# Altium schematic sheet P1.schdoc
size 594 x 419 mm; Symbol: Sheet-Symbol_A4; Company: 嘉立创EDA; Version: V1.0; Page Size: A4; @Project Name: fin; @Page Count: 1; @Update Date: 2026-05-17; @Create Date: 2026-05-17; @Schematic Name: Schematic1; @Page No: 1; @Page Name: P1; Device: Sheet-Symbol_A4; Border: 1; Title Block Position: 3; Width: 2338; Height: 1652; Region Start: 1; X Region Count: 6; Y Region Count: 4; Blade Width: 10; @Board Name: Board1; @Create Time: 12:38:21; @Update Time: 12:38:21
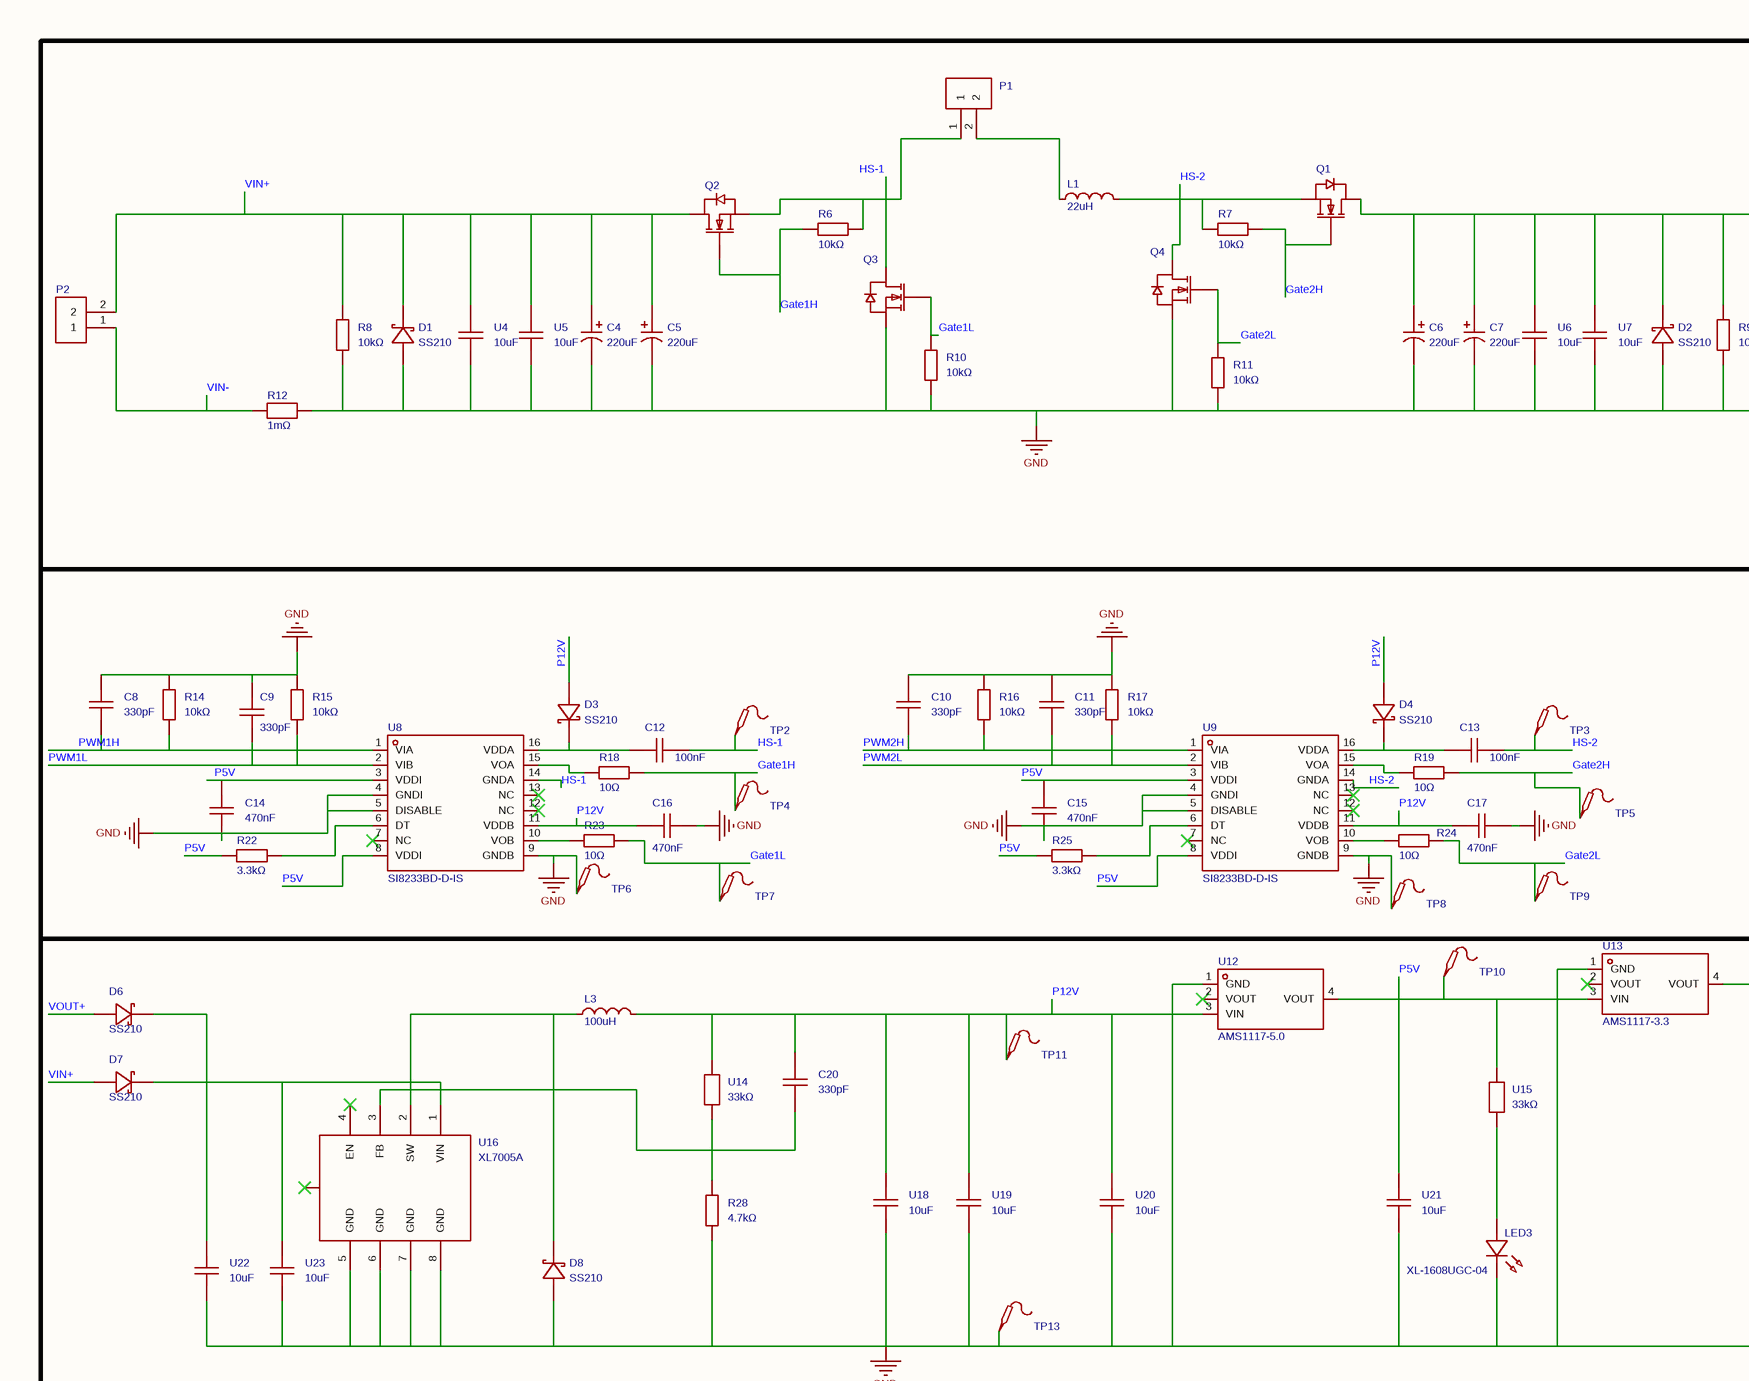
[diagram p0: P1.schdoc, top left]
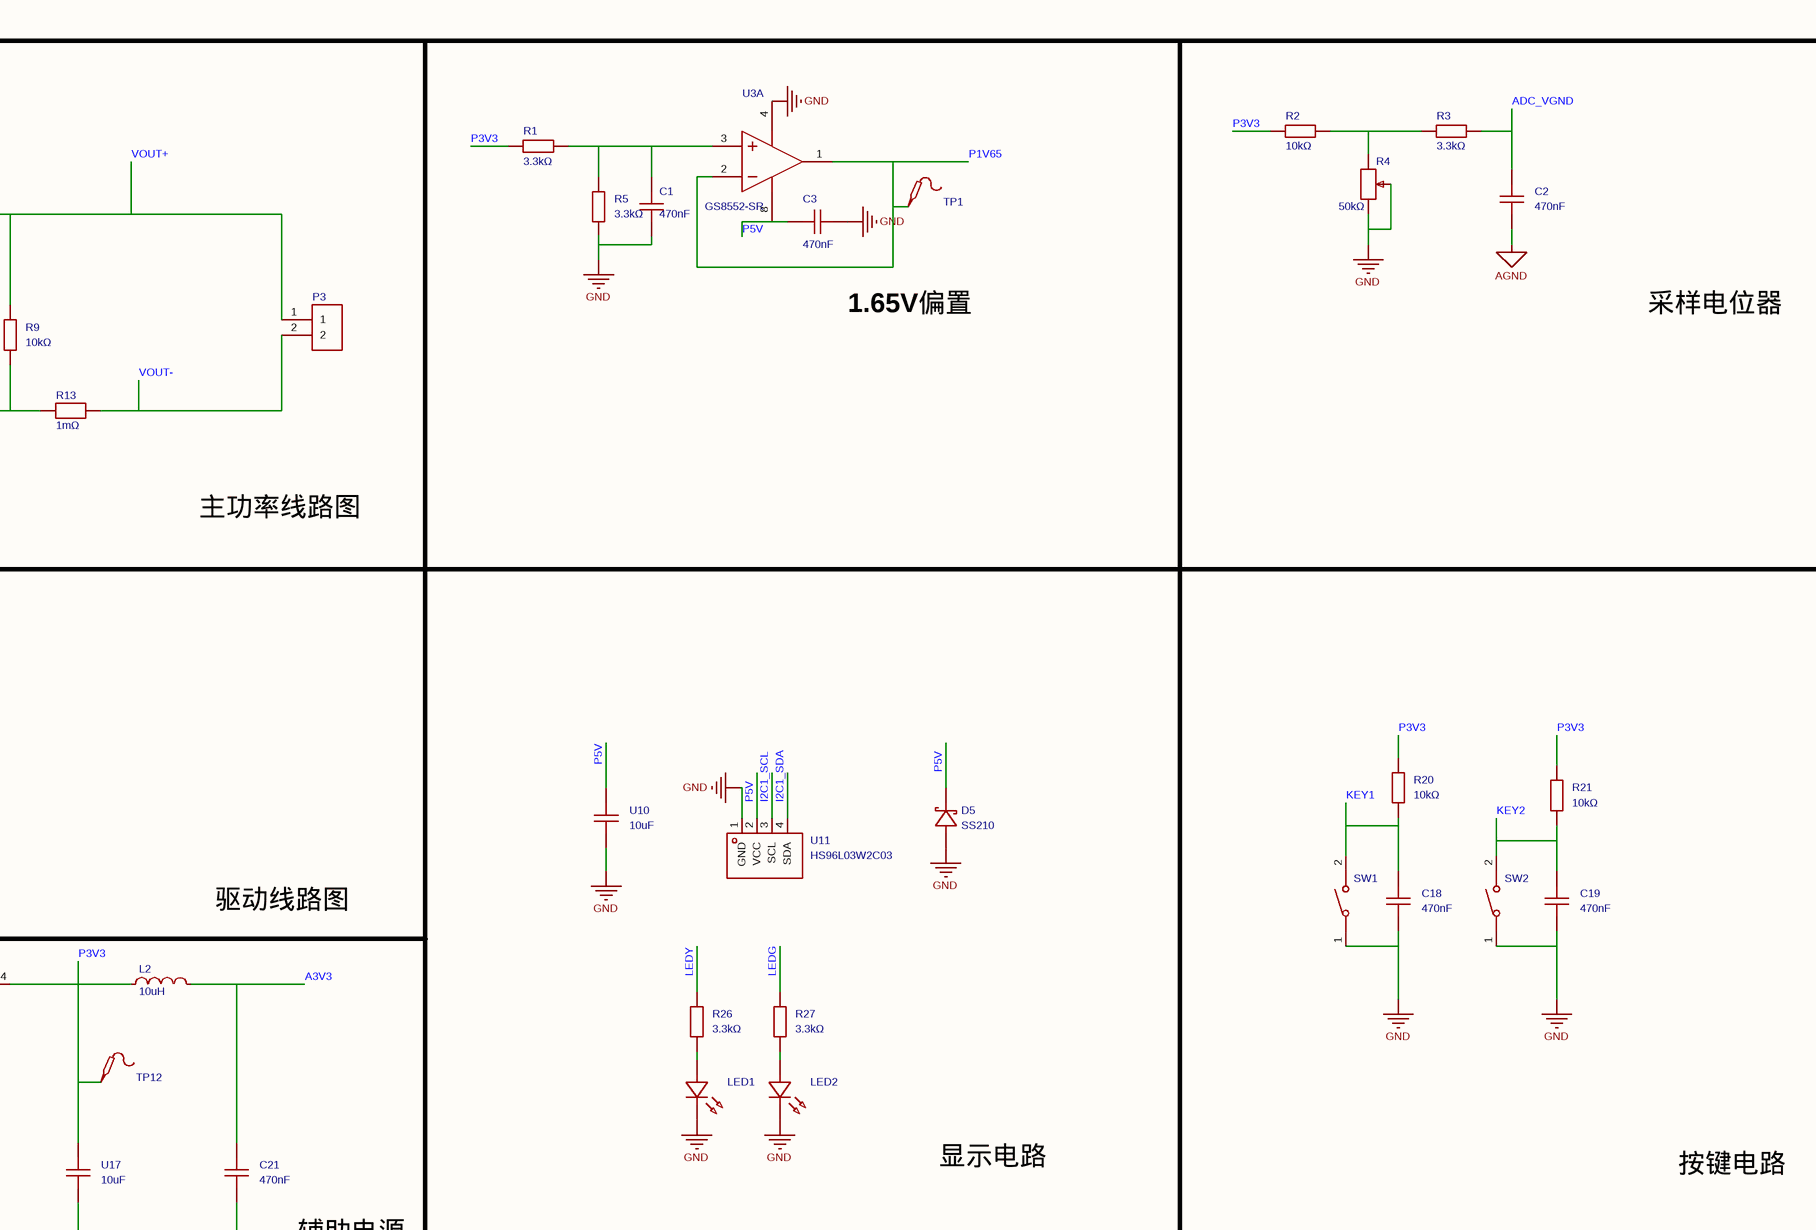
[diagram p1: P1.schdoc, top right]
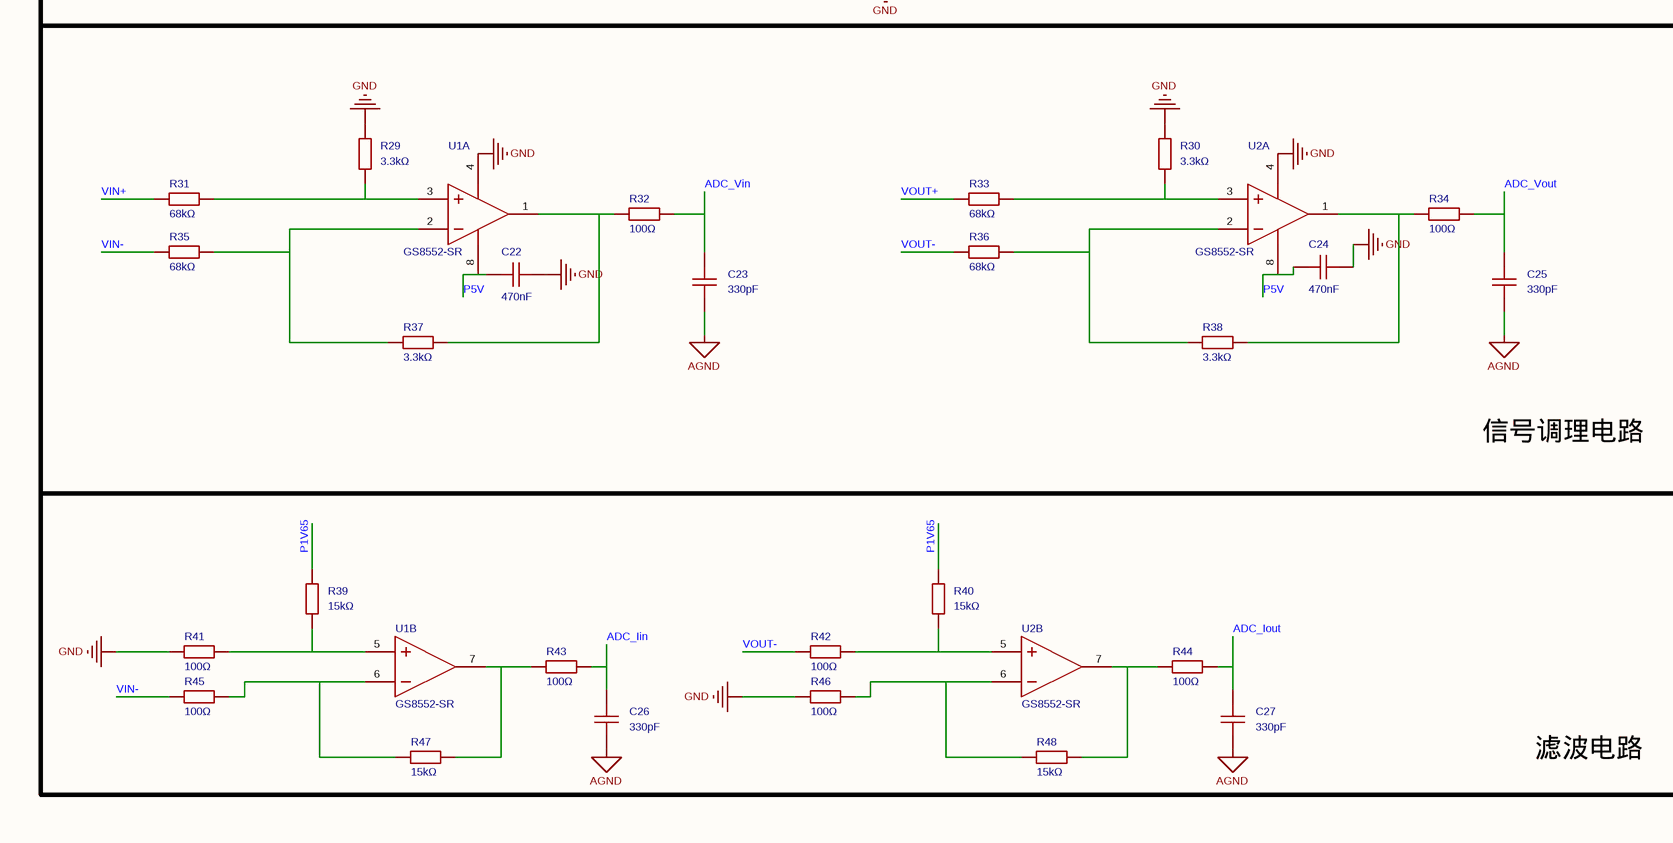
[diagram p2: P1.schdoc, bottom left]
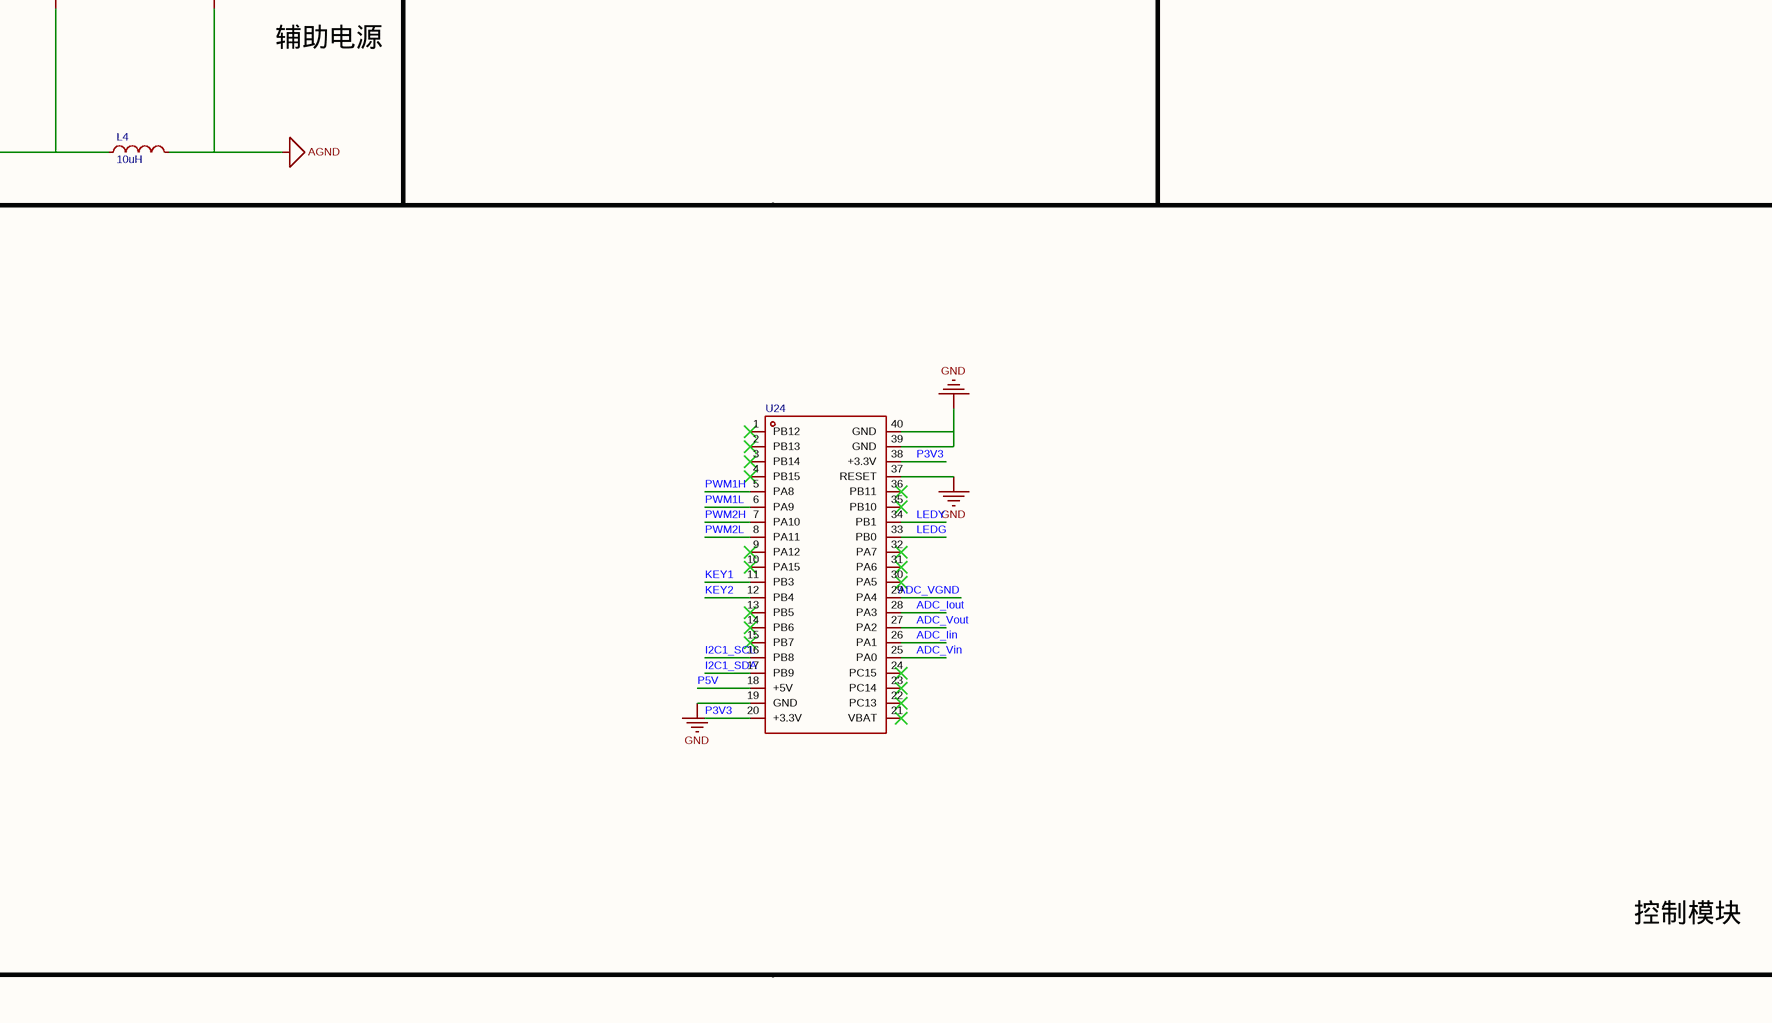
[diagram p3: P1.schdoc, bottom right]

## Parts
C1  470nF  [CAP-TH_L6.0-W5.0-P5.08-D0.5]
C2  470nF  [CAP-TH_L6.0-W5.0-P5.08-D0.5]
C3  470nF  [CAP-TH_L6.0-W5.0-P5.08-D0.5]
C4  220uF  [CAP-SMD_BD10.0-L10.3-W10.3-FD-LS11.0]
C5  220uF  [CAP-SMD_BD10.0-L10.3-W10.3-FD-LS11.0]
C6  220uF  [CAP-SMD_BD10.0-L10.3-W10.3-FD-LS11.0]
C7  220uF  [CAP-SMD_BD10.0-L10.3-W10.3-FD-LS11.0]
C8  330pF  [CAP-TH_L4.9-W3.7-P5.08-D0.5]
C9  330pF  [CAP-TH_L4.9-W3.7-P5.08-D0.5]
C10  330pF  [CAP-TH_L4.9-W3.7-P5.08-D0.5]
C11  330pF  [CAP-TH_L4.9-W3.7-P5.08-D0.5]
C12  100nF  [CAP-TH_L5.8-W3.6-P5.0-D0.6]
C13  100nF  [CAP-TH_L5.8-W3.6-P5.0-D0.6]
C14  470nF  [CAP-TH_L6.0-W5.0-P5.08-D0.5]
C15  470nF  [CAP-TH_L6.0-W5.0-P5.08-D0.5]
C16  470nF  [CAP-TH_L6.0-W5.0-P5.08-D0.5]
C17  470nF  [CAP-TH_L6.0-W5.0-P5.08-D0.5]
C18  470nF  [CAP-TH_L6.0-W5.0-P5.08-D0.5]
C19  470nF  [CAP-TH_L6.0-W5.0-P5.08-D0.5]
C20  330pF  [CAP-TH_L4.9-W3.7-P5.08-D0.5]
C21  470nF  [CAP-TH_L6.0-W5.0-P5.08-D0.5]
C22  470nF  [CAP-TH_L6.0-W5.0-P5.08-D0.5]
C23  330pF  [CAP-TH_L4.9-W3.7-P5.08-D0.5]
C24  470nF  [CAP-TH_L6.0-W5.0-P5.08-D0.5]
C25  330pF  [CAP-TH_L4.9-W3.7-P5.08-D0.5]
C26  330pF  [CAP-TH_L4.9-W3.7-P5.08-D0.5]
C27  330pF  [CAP-TH_L4.9-W3.7-P5.08-D0.5]
D1  SS210  [SMA_L4.3-W2.6-LS5.0-RD]
D2  SS210  [SMA_L4.3-W2.6-LS5.0-RD]
D3  SS210  [SMA_L4.3-W2.6-LS5.0-RD]
D4  SS210  [SMA_L4.3-W2.6-LS5.0-RD]
D5  SS210  [SMA_L4.3-W2.6-LS5.0-RD]
D6  SS210  [SMA_L4.3-W2.6-LS5.0-RD]
D7  SS210  [SMA_L4.3-W2.6-LS5.0-RD]
D8  SS210  [SMA_L4.3-W2.6-LS5.0-RD]
L1  22uH  [IND-SMD_2P-L16.9-W16.9]
L2  10uH  [L0603]
L3  100uH  [IND-SMD_L6.0-W6.0_CR6020]
L4  10uH  [L0603]
LED1  XL-1608UYC-06  [LED0603-RD-YELLOW]  (value not drawn)
LED2  XL-1608UGC-04  [LED0603-RD_GREEN]  (value not drawn)
LED3  XL-1608UGC-04  [LED0603-RD_GREEN]
P1  WJ500V-5.08-2P  [CONN-TH_2P-P5.00_WJ500V-5.08-2P]  (value not drawn)
P2  WJ500V-5.08-2P  [CONN-TH_2P-P5.00_WJ500V-5.08-2P]  (value not drawn)
P3  WJ500V-5.08-2P  [CONN-TH_2P-P5.00_WJ500V-5.08-2P]  (value not drawn)
Q1  IRFP4468PBF  [TO-247AC-3_L15.8-W5.0-P5.46-L]  (value not drawn)
Q2  IRFP4468PBF  [TO-247AC-3_L15.8-W5.0-P5.46-L]  (value not drawn)
Q3  IRFP4468PBF  [TO-247AC-3_L15.8-W5.0-P5.46-L]  (value not drawn)
Q4  IRFP4468PBF  [TO-247AC-3_L15.8-W5.0-P5.46-L]  (value not drawn)
R1  3.3kΩ  [RES-TH_BD2.2-L6.5-P10.50-D0.6]
R2  10kΩ  [RES-TH_BD4.5-L11.5-P15.50-D0.7]
R3  3.3kΩ  [RES-TH_BD2.2-L6.5-P10.50-D0.6]
R4  50kΩ  [RES-ADJ-TH_3296W]
R5  3.3kΩ  [RES-TH_BD2.2-L6.5-P10.50-D0.6]
R6  10kΩ  [RES-TH_BD4.5-L11.5-P15.50-D0.7]
R7  10kΩ  [RES-TH_BD4.5-L11.5-P15.50-D0.7]
R8  10kΩ  [RES-TH_BD4.5-L11.5-P15.50-D0.7]
R9  10kΩ  [RES-TH_BD4.5-L11.5-P15.50-D0.7]
R10  10kΩ  [RES-TH_BD4.5-L11.5-P15.50-D0.7]
R11  10kΩ  [RES-TH_BD4.5-L11.5-P15.50-D0.7]
R12  1mΩ  [R2512]
R13  1mΩ  [R2512]
R14  10kΩ  [RES-TH_BD4.5-L11.5-P15.50-D0.7]
R15  10kΩ  [RES-TH_BD4.5-L11.5-P15.50-D0.7]
R16  10kΩ  [RES-TH_BD4.5-L11.5-P15.50-D0.7]
R17  10kΩ  [RES-TH_BD4.5-L11.5-P15.50-D0.7]
R18  10Ω  [RES-TH_BD4.5-L11.5-P15.50-D0.7]
R19  10Ω  [RES-TH_BD4.5-L11.5-P15.50-D0.7]
R20  10kΩ  [RES-TH_BD4.5-L11.5-P15.50-D0.7]
R21  10kΩ  [RES-TH_BD4.5-L11.5-P15.50-D0.7]
R22  3.3kΩ  [RES-TH_BD2.2-L6.5-P10.50-D0.6]
R23  10Ω  [RES-TH_BD4.5-L11.5-P15.50-D0.7]
R24  10Ω  [RES-TH_BD4.5-L11.5-P15.50-D0.7]
R25  3.3kΩ  [RES-TH_BD2.2-L6.5-P10.50-D0.6]
R26  3.3kΩ  [RES-TH_BD2.2-L6.5-P10.50-D0.6]
R27  3.3kΩ  [RES-TH_BD2.2-L6.5-P10.50-D0.6]
R28  4.7kΩ  [RES-TH_BD2.3-L6.5-P10.50-D0.5]
R29  3.3kΩ  [RES-TH_BD2.2-L6.5-P10.50-D0.6]
R30  3.3kΩ  [RES-TH_BD2.2-L6.5-P10.50-D0.6]
R31  68kΩ  [RES-TH_BD4.5-L11.5-P15.50-D0.7]
R32  100Ω  [RES-TH_BD5.0-L15.5-P19.50-D0.70]
R33  68kΩ  [RES-TH_BD4.5-L11.5-P15.50-D0.7]
R34  100Ω  [RES-TH_BD5.0-L15.5-P19.50-D0.70]
R35  68kΩ  [RES-TH_BD4.5-L11.5-P15.50-D0.7]
R36  68kΩ  [RES-TH_BD4.5-L11.5-P15.50-D0.7]
R37  3.3kΩ  [RES-TH_BD2.2-L6.5-P10.50-D0.6]
R38  3.3kΩ  [RES-TH_BD2.2-L6.5-P10.50-D0.6]
R39  15kΩ  [RES-TH_BD2.2-L6.5-P10.50-D0.6]
R40  15kΩ  [RES-TH_BD2.2-L6.5-P10.50-D0.6]
R41  100Ω  [RES-TH_BD5.0-L15.5-P19.50-D0.70]
R42  100Ω  [RES-TH_BD5.0-L15.5-P19.50-D0.70]
R43  100Ω  [RES-TH_BD5.0-L15.5-P19.50-D0.70]
R44  100Ω  [RES-TH_BD5.0-L15.5-P19.50-D0.70]
R45  100Ω  [RES-TH_BD5.0-L15.5-P19.50-D0.70]
R46  100Ω  [RES-TH_BD5.0-L15.5-P19.50-D0.70]
R47  15kΩ  [RES-TH_BD2.2-L6.5-P10.50-D0.6]
R48  15kΩ  [RES-TH_BD2.2-L6.5-P10.50-D0.6]
SW1  TS-1088-AR02016  [SW-SMD_L3.9-W3.0-P4.45]  (value not drawn)
SW2  TS-1088-AR02016  [SW-SMD_L3.9-W3.0-P4.45]  (value not drawn)
TP1  (no value)  [Test-Point-0.5mm]
TP2  (no value)  [Test-Point-0.5mm]
TP3  (no value)  [Test-Point-0.5mm]
TP4  (no value)  [Test-Point-0.5mm]
TP5  (no value)  [Test-Point-0.5mm]
TP6  (no value)  [Test-Point-0.5mm]
TP7  (no value)  [Test-Point-0.5mm]
TP8  (no value)  [Test-Point-0.5mm]
TP9  (no value)  [Test-Point-0.5mm]
TP10  (no value)  [Test-Point-0.5mm]
TP11  (no value)  [Test-Point-0.5mm]
TP12  (no value)  [Test-Point-0.5mm]
TP13  (no value)  [Test-Point-0.5mm]
U1  GS8552-SR  [SOIC-8_L4.9-W3.9-P1.27-LS6.0-BL]  (parts A,B of 2)
U2  GS8552-SR  [SOIC-8_L4.9-W3.9-P1.27-LS6.0-BL]  (parts A,B of 2)
U3  GS8552-SR  [SOIC-8_L4.9-W3.9-P1.27-LS6.0-BL]  (part A of 2)
U4  10uF  [CAP-TH_L5.5-W3.8-P5.08-D0.5]
U5  10uF  [CAP-TH_L5.5-W3.8-P5.08-D0.5]
U6  10uF  [CAP-TH_L5.5-W3.8-P5.08-D0.5]
U7  10uF  [CAP-TH_L5.5-W3.8-P5.08-D0.5]
U8  SI8233BD-D-IS  [SOIC-16_L10.3-W7.5-P1.27-LS10.3-BL]
U9  SI8233BD-D-IS  [SOIC-16_L10.3-W7.5-P1.27-LS10.3-BL]
U10  10uF  [CAP-TH_L5.5-W3.8-P5.08-D0.5]
U11  HS96L03W2C03  [OLED-TH_L27.8-W27.2-P2.54_C9900033791]
U12  AMS1117-5.0  [SOT-223_L6.5-W3.5-P2.30-LS7.0-BR]
U13  AMS1117-3.3  [SOT-223-3_L6.5-W3.4-P2.30-LS7.0-BR]
U14  33kΩ  [RES-TH_BD2.4-L6.3-P10.30-D0.6]
U15  33kΩ  [RES-TH_BD2.4-L6.3-P10.30-D0.6]
U16  XL7005A  [SOIC-8_L4.9-W3.9-P1.27-LS6.0-BL-EP3.1-1]
U17  10uF  [CAP-TH_L5.5-W3.8-P5.08-D0.5]
U18  10uF  [CAP-TH_L5.5-W3.8-P5.08-D0.5]
U19  10uF  [CAP-TH_L5.5-W3.8-P5.08-D0.5]
U20  10uF  [CAP-TH_L5.5-W3.8-P5.08-D0.5]
U21  10uF  [CAP-TH_L5.5-W3.8-P5.08-D0.5]
U22  10uF  [CAP-TH_L5.5-W3.8-P5.08-D0.5]
U23  10uF  [CAP-TH_L5.5-W3.8-P5.08-D0.5]
U24  LCKFB-DKX-STM32F103C8T6  [CONN-TH_L53.3-W22.9_STM32F103C8T6-CARD]  (value not drawn)

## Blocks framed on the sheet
主功率线路图: C4-C7 D1 D2 L1 P1-P3 Q1-Q4 R6-R13 U4-U7
驱动线路图: C8-C17 D3 D4 R14-R19 R22-R25 TP2-TP9 U8 U9
信号调理电路: C22-C25 R29-R38 U1 U2

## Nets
AGND: C2.1 C21.1 C23.1 C25.1 C26.1 C27.1 L4.2
GND: C1.1 C3.1 C4.2 C5.2 C6.2 C7.2 C8.2 C9.2 C10.2 C11.2 C14.1 C15.1 C16.1 C17.1 C18.1 C19.1 C22.1 C24.1 D1.2(A) D2.2(A) D5.2(A) D8.2(A) L4.1 LED1.1(K) LED2.1(K) LED3.1(K) Q3.3(S) Q4.3(S) R4.2 R4.3 R5.1 R8.1 R9.1 R10.2 R11.2 R12.2 R13.2 R14.2 R15.2 R16.2 R17.2 R28.1 R29.2 R30.2 R41.1 R46.1 SW1.1 SW2.1 TP6.1 TP8.1 TP13.1 U1.4(-V) U2.4(-V) U3.4(-V) U4.1 U5.1 U6.1 U7.1 U8.4(GNDI) U8.5(DISABLE) U8.9(GNDB) U9.4(GNDI) U9.5(DISABLE) U9.9(GNDB) U10.1 U11.1(GND) U12.1(GND) U13.1(GND) U16.5(GND) U16.6(GND) U16.7(GND) U16.8(GND) U17.1 U18.1 U19.1 U20.1 U21.1 U22.1 U23.1 U24.19(GND) U24.37(RESET) U24.39(GND) U24.40(GND)
A3V3: C21.2 L2.2
ADC_Iin: C26.2 R43.2 U24.26(PA1)
ADC_Iout: C27.2 R44.2 U24.28(PA3)
ADC_VGND: C2.2 R3.2 U24.29(PA4)
ADC_Vin: C23.2 R32.2 U24.25(PA0)
ADC_Vout: C25.2 R34.2 U24.27(PA2)
Gate1H: Q2.1(G) R6.2 R18.2 TP4.1
Gate1L: Q3.1(G) R10.1 R23.2 TP7.1
Gate2H: Q1.1(G) R7.1 R19.2 TP5.1
Gate2L: Q4.1(G) R11.1 R24.2 TP9.1
HS-1: C12.2 P1.1 Q2.3(S) Q3.2(D) R6.1 TP2.1 U8.14(GNDA)
HS-2: C13.2 L1.2 Q1.3(S) Q4.2(D) R7.2 TP3.1 U9.14(GNDA)
I2C1_SCL: U11.3(SCL) U24.16(PB8)
I2C1_SDA: U11.4(SDA) U24.17(PB9)
KEY1: C18.2 R20.1 SW1.2 U24.11(PB3)
KEY2: C19.2 R21.1 SW2.2 U24.12(PB4)
LEDG: R27.2 U24.33(PB0)
LEDY: R26.2 U24.34(PB1)
P1V65: R39.2 R40.2 TP1.1 U3.1(OUT) U3.2(INVERTING_INPUT)
P3V3: L2.1 R1.1 R2.2 R20.2 R21.2 TP12.1 U13.4(VOUT) U17.2 U24.20(+3.3V) U24.38(+3.3V)
P5V: C3.2 C14.2 C15.2 C22.2 C24.2 D5.1(K) R22.1 R25.1 TP10.1 U1.8(+V) U2.8(+V) U3.8(+V) U8.3(VDDI) U8.8(VDDI) U9.3(VDDI) U9.8(VDDI) U10.2 U11.2(VCC) U12.4(VOUT) U13.3(VIN) U15.2 U21.2 U24.18(+5V)
P12V: C16.2 C17.2 C20.2 D3.2(A) D4.2(A) L3.2 TP11.1 U8.11(VDDB) U9.11(VDDB) U12.3(VIN) U14.2 U18.2 U19.2 U20.2
PWM1H: C8.1 R14.1 U8.1(VIA) U24.5(PA8)
PWM1L: C9.1 R15.1 U8.2(VIB) U24.6(PA9)
PWM2H: C10.1 R16.1 U9.1(VIA) U24.7(PA10)
PWM2L: C11.1 R17.1 U9.2(VIB) U24.8(PA11)
VIN+: C4.1 C5.1 D1.1(K) D7.2(A) P2.2 Q2.2(D) R8.2 R31.1 U4.2 U5.2
VIN-: P2.1 R12.1 R35.1 R45.1
VOUT+: C6.1 C7.1 D2.1(K) D6.2(A) P3.1 Q1.2(D) R9.2 R33.1 U6.2 U7.2
VOUT-: P3.2 R13.1 R36.1 R42.1
NetC1_2: C1.2 R1.2 R5.2 U3.3(NONINVERTING_INPUT)
NetC12_1: C12.1 D3.1(K) U8.16(VDDA)
NetC13_1: C13.1 D4.1(K) U9.16(VDDA)
NetC20_1: C20.1 R28.2 U14.1 U16.3(FB)
NetD6_1: D6.1(K) D7.1(K) U16.1(VIN) U22.2 U23.2
NetD8_1: D8.1(K) L3.1 U16.2(SW)
NetL1_1: L1.1 P1.2
NetLED1_2: LED1.2(A) R26.1
NetLED2_2: LED2.2(A) R27.1
NetLED3_2: LED3.2(A) U15.1
NetR2_1: R2.1 R3.1 R4.1
NetR18_1: R18.1 U8.15(VOA)
NetR19_1: R19.1 U9.15(VOA)
NetR22_2: R22.2 U8.6(DT)
NetR23_1: R23.1 U8.10(VOB)
NetR24_1: R24.1 U9.10(VOB)
NetR25_2: R25.2 U9.6(DT)
NetR29_1: R29.1 R31.2 U1.3(NONINVERTING_INPUT)
NetR30_1: R30.1 R33.2 U2.3(NONINVERTING_INPUT)
NetR32_1: R32.1 R37.2 U1.1(OUT)
NetR34_1: R34.1 R38.2 U2.1(OUT)
NetR35_2: R35.2 R37.1 U1.2(INVERTING_INPUT)
NetR36_2: R36.2 R38.1 U2.2(INVERTING_INPUT)
NetR39_1: R39.1 R41.2 U1.5(NONINVERTING_INPUT)
NetR40_1: R40.1 R42.2 U2.5(NONINVERTING_INPUT)
NetR43_1: R43.1 R47.2 U1.7(OUT)
NetR44_1: R44.1 R48.2 U2.7(OUT)
NetR45_2: R45.2 R47.1 U1.6(INVERTING_INPUT)
NetR46_2: R46.2 R48.1 U2.6(INVERTING_INPUT)

Not connected (* = marked no-connect by the designer): U8 7(NC)* 12(NC)* 13(NC)*; U9 7(NC)* 12(NC)* 13(NC)*; U12 2(VOUT)*; U13 2(VOUT)*; U16 4(EN)* 9*; U24 1(PB12)* 2(PB13)* 3(PB14)* 4(PB15)* 9(PA12)* 10(PA15)* 13(PB5)* 14(PB6)* 15(PB7)* 21(VBAT)* 22(PC13)* 23(PC14)* 24(PC15)* 30(PA5)* 31(PA6)* 32(PA7)* 35(PB10)* 36(PB11)*

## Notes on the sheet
- 1.65V偏置
- 采样电位器
- 显示电路
- 按键电路
- 辅助电源
- 滤波电路
- 控制模块

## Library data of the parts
C1-C3 C14-C19 C21 C22 C24 = CT4-1206B474K101F3-Y: 容值:470nF;精度:±10%;额定电压:100V;; Manufacturer: KYET(科雅); AddInBom: yes; ModelId: 5366a4b42989498ea42b999c17b4cd530819f05c4eef4c71ace90d822a990e87; ModelTransform: 236.22,197.2437,0,0,0,0,0,0,-196.85; Tolerance: ±10%; Voltage Rating: 100V; Pin Spacing: 5.08mm
C4-C7 = JVJ63V220M10x10: 容值:220uF;精度:±20%;额定电压:63V;纹波电流:225mA@120Hz;; Manufacturer: JIERR(捷而瑞); AddInBom: yes; ModelId: c5805980ffa24e6da624be5898d1d67f0819f05c4eef4c71ace90d822a990e87; ModelTransform: 433.07,405.511,0,180,0,0,0,0,0; Tolerance: ±20%; Voltage Rating: 63V; Lifetime: 2000hrs@105℃
C8-C11 C20 C23 C25-C27 = CL0805CG100V331JS: 容值:330pF;精度:±5%;额定电压:100V;温度系数:COG;; Manufacturer: TORCH(火炬); AddInBom: yes; ModelId: d480a48107b54a3595d34e62c8baa7590819f05c4eef4c71ace90d822a990e87; ModelName: CAP-TH_L4.9-W3.7-H2.5-P5.08; ModelTransform: 215.7476,125.984,0,0,0,0,0,0,-137.795; Tolerance: ±5%; Voltage Rating: 100V; Temperature Coefficient: COG; Pin Spacing: 5.08mm
C12 C13 = 178MU0002: 容值:100nF;精度:±10%;额定电压:50V;温度系数:X7R;; Manufacturer: KNSCHA(科尼盛); AddInBom: yes; ModelId: 67fba78a874e4dacbebdaf42387313520819f05c4eef4c71ace90d822a990e87; ModelTransform: 228.346,142.1257,0,0,0,0,0,0,-196.85; Tolerance: ±10%; Voltage Rating: 50V; Temperature Coefficient: X7R; Pin Spacing: 5.08mm
D1-D4 D6-D8 = SS210_C18199175: 二极管配置:独立式;正向压降(Vf):850mV@2A;直流反向耐压(Vr):100V;整流电流:2A;; Manufacturer: R+O(宏嘉诚); AddInBom: yes; ModelId: 8d2dd2e50a3a4b27821fa63d469a8f110819f05c4eef4c71ace90d822a990e87; ModelTransform: 196.85,102.362,0,0,0,0,0,0,0; Diode Configuration: 独立式; Voltage - DC Reverse(Vr): 100V; Current - Rectified: 2A; Reverse Leakage Current (Ir): 50uA@100V; Operating Junction Temperature Range: -55℃~+150℃; Non-Repetitive Peak Forward Surge Current: 50A
D5 = SS210_C18199175: 二极管配置:独立式;正向压降(Vf):850mV@2A;直流反向耐压(Vr):100V;整流电流:2A;; Manufacturer: R+O(宏嘉诚); 3D Model: 8d2dd2e50a3a4b27821fa63d469a8f110819f05c4eef4c71ace90d822a990e87; 3D Model Transform: 196.85,102.362,0,0,0,0,0,0,0; Diode Configuration: 独立式; Voltage - DC Reverse(Vr): 100V; Current - Rectified: 2A; Reverse Leakage Current (Ir): 50uA@100V; Operating Junction Temperature Range: -55℃~+150℃; Non-Repetitive Peak Forward Surge Current: 50A; AddInBom: yes
L1 = MDA1870-220M: 电感值:22uH;精度:±20%;额定电流:13.5A;饱和电流(Isat):13.5A;直流电阻(DCR):20.5mΩ;; Manufacturer: KOHERelec(科或); AddInBom: yes; ModelId: 69014a8d40644ee482cb69c22c4ffe030819f05c4eef4c71ace90d822a990e87; ModelTransform: 692.912,665.353,0,0,0,0,0,0,0; Tolerance: ±20%; Current Rating: 13.5A; DC Resistance(DCR): 20.5mΩ
L2 L4 = SDFL1608S100KTF: 电感值:10uH;精度:±10%;额定电流:3mA;饱和电流(Isat):-;直流电阻(DCR):1.85Ω;; Manufacturer: Sunlord(顺络); AddInBom: yes; ModelId: 2bc5ec593d464d6ba9807aec0b5673c20819f05c4eef4c71ace90d822a990e87; ModelName: L0603_L1.6-W0.8-H0.5_BEAD; ModelTransform: 62.992,31.496,0,180,0,0,0.094,0.629,0; Tolerance: ±10%; Current Rating: 3mA; DC Resistance(DCR): 1.85Ω; Q @ Frequency: 30@2MHz; Frequency - Self Resonant: 17MHz
L3 = CR6020-101M: 电感值:100uH;精度:±20%;额定电流:500mA;饱和电流(Isat):550mA;; Manufacturer: ceaiya(柯爱亚); AddInBom: yes; ModelId: 6ed5412c8907432393ddf32fe89ec5c30819f05c4eef4c71ace90d822a990e87; ModelTransform: 236.22,236.22,0,0,0,0,0,0,0; Tolerance: ±20%; Current Rating: 500mA; Current - Saturation(Isat): 550mA; DC Resistance(DCR): 1.15Ω
LED1 = XL-1608UYC-06: 灯头类型:-;发光颜色:黄色;正向压降(Vf):2.4V;功率:50mW;正向电流:20mA;波长:585nm~595nm;二极管配置:独立二极管;透镜颜色:无色透明透镜;色温:-;发光强度:435mcd;发光角度:120°;载带方式:正贴;工作温度:-40℃~+85℃;; Manufacturer: XINGLIGHT(成兴光); 3D Model: a8fc7d5425514cf49dd600af0a7bb2230819f05c4eef4c71ace90d822a990e87; 3D Model Transform: 63.7794,32.283,0,0,0,0,-1.969,0,0; Illumination Color: 黄色; Voltage - Forward(Vf): 2.4V; Power(Watts): 50mW; Forward Current: 20mA; Peak Wavelength: 590nm; Diode Configuration: 独立二极管; Lens Color: 无色透明透镜; Luminous Intensity: 435mcd; Viewing Angle: 120°; AddInBom: yes
LED2 = XL-1608UGC-04: 灯头类型:-;发光颜色:翠绿色;正向压降(Vf):3.3V;功率:70mW;正向电流:20mA;波长:515nm~535nm;二极管配置:独立二极管;透镜颜色:无色透明透镜;色温:-;发光强度:810mcd;发光角度:120°;载带方式:正贴;工作温度:-40℃~+85℃;; Manufacturer: XINGLIGHT(成兴光); 3D Model: 7761174b67d9475ab0dbce38062fb2f90819f05c4eef4c71ace90d822a990e87; 3D Model Transform: 63.7794,31.496,0,0,0,0,0,0,0; Illumination Color: 翠绿色; Voltage - Forward(Vf): 3.3V; Power(Watts): 70mW; Forward Current: 20mA; Peak Wavelength: 525nm; Diode Configuration: 独立二极管; Lens Color: 无色透明透镜; Luminous Intensity: 810mcd; Viewing Angle: 120°; AddInBom: yes
LED3 = XL-1608UGC-04: 灯头类型:-;发光颜色:翠绿色;正向压降(Vf):3.3V;功率:70mW;正向电流:20mA;波长:515nm~535nm;二极管配置:独立二极管;透镜颜色:无色透明透镜;色温:-;发光强度:810mcd;发光角度:120°;载带方式:正贴;工作温度:-40℃~+85℃;; Manufacturer: XINGLIGHT(成兴光); AddInBom: yes; ModelId: 7761174b67d9475ab0dbce38062fb2f90819f05c4eef4c71ace90d822a990e87; ModelTransform: 63.7794,31.496,0,0,0,0,0,0,0; Illumination Color: 翠绿色; Voltage - Forward(Vf): 3.3V; Power(Watts): 70mW; Forward Current: 20mA; Peak Wavelength: 525nm; Diode Configuration: 独立二极管; Lens Color: 无色透明透镜; Luminous Intensity: 810mcd; Viewing Angle: 120°
P1-P3 = WJ500V-5.08-2P: 结构:1x2P;间距:5.08mm;颜色:绿色;安装方式:直插;额定电流:18A;额定电压:250V;排数:1;线规 - AWG:14~30;线规 - 平方毫米:2.5;每排PIN数:2;触头材质:-;触头镀层:-;工作温度范围:-40℃~+105℃;焊接温度(最大值):-;; Manufacturer: KANGNEX(康奈克斯电气); Symbol: WJ500V-5.08-2P-14-00A; AddInBom: yes; ModelId: 0f4a503c8d3b4ae19ed61267f5e9a1d70819f05c4eef4c71ace90d822a990e87; ModelTransform: 423.621,393.7,0,0,0,0,-11.811,19.685,-137.795; Structure: 1x2P; Pitch: 5.08mm; Current Rating (Max): 18A; Voltage Rating (Max): 250V; Wire Gauge - AWG: 14~30; Wire Gauge - mm2: 2.5; Number of PINs Per Row: 2; Screw Specification: M2.5
Q1-Q4 = IRFP4468PBF: 类型:1个N沟道;漏源电压(Vdss):100V;连续漏极电流(Id):290A;导通电阻(RDS(on)@Vgs,Id):2.6mΩ@10V,180A;功率(Pd):520W;阈值电压(Vgs(th)@Id):4V@250uA;; Manufacturer: Infineon(英飞凌); Add into BOM: yes; 3D Model: 6e387369c9904836bdc1f26e11437a00; 3D Model Transform: 622.046,196.88937,0,0,0,0,0,-11.811,-137.795; Reverse Transfer Capacitance (Crss@Vds): 540pF; Type: 1个N沟道; Drain Source Voltage (Vdss): 100V; Continuous Drain Current (Id): 290A; Power Dissipation (Pd): 520W; Total Gate Charge (Qg@Vgs): 540nC; Input Capacitance (Ciss@Vds): 19.86nF; ModelName: TO-247AC-3_L15.8-W5.0-H20.5-P5.46
R1 R3 R5 R22 R25-R27 R29 R30 R37 R38 = MFR0W4F3301A50: 电阻类型:金属膜电阻;阻值:3.3kΩ;精度:±1%;功率:250mW;温度系数:±50ppm/℃;; Manufacturer: UNI-ROYAL(厚声); AddInBom: yes; ModelId: 259c3103781c424fb695c8049f0a17f30819f05c4eef4c71ace90d822a990e87; ModelTransform: 437.007,91.18383,0,0,0,0,0,0,-137.795; Tolerance: ±1%; Voltage-Supply(Max): 250V; Power(Watts): 250mW
R2 R6-R10 R14-R17 R20 R21 = MFR01SF1002A10: 电阻类型:金属膜电阻;阻值:10kΩ;精度:±1%;功率:1W;温度系数:±50ppm/℃;; Manufacturer: UNI-ROYAL(厚声); AddInBom: yes; ModelId: 8cdc597c9b3f496195c9a4ae737df7de0819f05c4eef4c71ace90d822a990e87; ModelName: RES-TH_BD4.5-L11.5-P15.50; ModelTransform: 633.857,177.952,0,0,0,0,0,0,-137.795; Tolerance: ±1%; Voltage-Supply(Max): 350V; Power(Watts): 1W
R4 = 3296W-1-503LF_C49190466: 阻值:50kΩ;精度:±10%;功率:500mW;温度系数:±150ppm/℃;; Manufacturer: JIERR(捷而瑞); 3D Model: 3664f7b541aa4725a8b6d3b7a961f0780819f05c4eef4c71ace90d822a990e87; 3D Model Transform: 374.015,188.976,0,90,0,0,2.362,0.005,-137.795; Tolerance: ±10%; Power(Watts): 500mW; Number of Turns: 28; AddInBom: yes
R11 = MFR01SF1002A10: 电阻类型:金属膜电阻;阻值:10kΩ;精度:±1%;功率:1W;温度系数:±50ppm/℃;; Manufacturer: UNI-ROYAL(厚声); 3D Model: 8cdc597c9b3f496195c9a4ae737df7de0819f05c4eef4c71ace90d822a990e87; 3D Model Transform: 633.857,177.952,0,0,0,0,0,0,-137.795; Tolerance: ±1%; Voltage-Supply(Max): 350V; Power(Watts): 1W; AddInBom: yes; ModelName: RES-TH_BD4.5-L11.5-P15.50
R12 R13 = JER2512F3R001L: 电阻类型:采样电阻；合金电阻;阻值:1mΩ;精度:±1%;功率:3W;温度系数:±50ppm/℃;; Manufacturer: JIERR(捷而瑞); AddInBom: yes; ModelId: 954b67263d9e4f3582d8de3f8c8464210819f05c4eef4c71ace90d822a990e87; ModelName: R2512_L6.3-W3.2-H0.6; ModelTransform: 248.031,125.984,0,0,0,0,-0.0005,0,0; Tolerance: ±1%; Power(Watts): 3W
R18 R19 R23 R24 = MOR02SJ0100A10: 电阻类型:金属氧化膜电阻;阻值:10Ω;精度:±5%;功率:2W;温度系数:±350ppm/℃;; Manufacturer: UNI-ROYAL(厚声); AddInBom: yes; ModelId: 8cdc597c9b3f496195c9a4ae737df7de0819f05c4eef4c71ace90d822a990e87; ModelName: RES-TH_BD4.5-L11.5-P15.50; ModelTransform: 633.857,177.952,0,0,0,0,0,0,-137.795; Tolerance: ±5%; Voltage-Supply(Max): 350V; Power(Watts): 2W
R28 = MF1/4W-4.7KΩ±1% T: 电阻类型:金属膜电阻;阻值:4.7kΩ;精度:±1%;功率:250mW;温度系数:±100ppm/℃;; Manufacturer: CCO(千志电子); Symbol: MF1/4W-4.7KΩ±1% T52; AddInBom: yes; ModelId: 8e6c7ee8323443d1ab8f0504b6353c8c0819f05c4eef4c71ace90d822a990e87; ModelName: RES-TH_D2.3-L6.5-P10.50; ModelTransform: 431.1015,91.3384,0,0,0,0,0.197,0,-137.795; Tolerance: ±1%; Voltage-Supply(Max): 250V; Power(Watts): 250mW
R31 R33 R35 R36 = MF2WS-68KΩ±1% T: 电阻类型:金属膜电阻;阻值:68kΩ;精度:±1%;功率:2W;温度系数:±100ppm/℃;; Manufacturer: CCO(千志电子); AddInBom: yes; ModelId: 8cdc597c9b3f496195c9a4ae737df7de0819f05c4eef4c71ace90d822a990e87; ModelName: RES-TH_BD4.5-L11.5-P15.50; ModelTransform: 633.857,177.952,0,0,0,0,0,0,-137.795; Tolerance: ±1%; Voltage-Supply(Max): 350V; Power(Watts): 2W
R32 R34 R41-R46 = MFR02SF1000A10: 电阻类型:金属膜电阻;阻值:100Ω;精度:±1%;功率:2W;温度系数:±50ppm/℃;; Manufacturer: UNI-ROYAL(厚声); AddInBom: yes; ModelId: fc5c109b76f247e2a5028dac0cfd05ca0819f05c4eef4c71ace90d822a990e87; ModelTransform: 795.27392,196.37071,0,0,0,0,0,0,-118.11; Tolerance: ±1%; Voltage-Supply(Max): 500V; Power(Watts): 2W
R39 R40 R47 R48 = MFR0W4F1502A50: 电阻类型:金属膜电阻;阻值:15kΩ;精度:±1%;功率:250mW;温度系数:±50ppm/℃;; Manufacturer: UNI-ROYAL(厚声); AddInBom: yes; ModelId: 259c3103781c424fb695c8049f0a17f30819f05c4eef4c71ace90d822a990e87; ModelTransform: 437.007,91.18383,0,0,0,0,0,0,-137.795; Tolerance: ±1%; Voltage-Supply(Max): 250V; Power(Watts): 250mW
SW1 SW2 = TS-1088-AR02016: 电路结构:单刀单掷;按钮形状:圆形按钮;作用力:1.6N;安装方式:立贴;开关长度:4mm;开关宽度:3mm;开关高度:2mm;带支架:不带支架;触点电流:50mA;额定电压:12V;工作寿命:10万次;; Manufacturer: XUNPU(讯普); 3D Model: b26698b69f274ffabef8a26c7d0e5dd10819f05c4eef4c71ace90d822a990e87; 3D Model Transform: 188.976,114.174,0,0,0,0,0,0,0; Circuit: 单刀单掷; Actuator Style: 圆形按钮; Operating Force: 1.6N; Switch Height: 2mm; with Bracket: 不带支架; Contact Current: 50mA; Voltage Rating: 12V; Actuator/Cap Color: 黑色; Life: 10万次; AddInBom: yes; ModelName: SW-SMD_L3.9-W2.9-H2.0-LS4.8
TP1-TP13 = Test-Point: Test Point 测试点; AddInBom: yes
U1-U3 = GS8552-SR: 放大器数:双路;增益带宽积(GBP):1.8MHz;输入偏置电流(Ib):20pA;输入失调电压(Vos):30uV;压摆率(SR):0.95V/us;轨到轨:轨到轨输入,轨到轨输出;; Manufacturer: Gainsil(聚洵); Relevance: []; 3D Model: e81d2f7d937b4a6ab1dca543ff5d56a40819f05c4eef4c71ace90d822a990e87; 3D Model Transform: 192.913,236.22,0,0,0,0,0,0,0; Number of Channels: 双路; Gain Bandwidth Product: 1.8MHz; Ib - Input Bias Current: 20pA; Vos - Input Offset Voltage: 30uV; Common Mode Rejection Ratio(CMRR): 110dB; Output Current: 65mA; Input Offset Voltage Drift(Vos TC): 10nV/℃; Quiescent Current(Iq): 180uA; Single Supply: 1.8V~5.5V; Dual Supply: 900mV~2.75V；-2.75V~-900mV; Maximum Power Supply Range (Vdd-Vss): 5.5V; Noise density(eN): 38nV/√Hz@1kHz; Input Offset Current(Ios): 10pA; AddInBom: yes; ModelName: SOIC-8_L4.9-W3.9-H1.7-LS6.0-P1.27
U4-U7 U10 U17-U23 = CD1H106KC9IER2F100: 容值:10uF;精度:±10%;额定电压:50V;温度系数:X5R;; Manufacturer: Dersonic(德尔创); AddInBom: yes; ModelId: 30ed28be0b3b4d15a702e5d47761fb1d0819f05c4eef4c71ace90d822a990e87; ModelName: CAP-TH_L4.2-W3.8-H3.8-P5.08; ModelTransform: 215.7476,118.11,0,0,0,0,0,0,-137.795; Tolerance: ±10%; Voltage Rating: 50V; Temperature Coefficient: X5R; Pin Spacing: 5.08mm
U8 U9 = SI8233BD-D-IS: 驱动配置:低边；高边;负载类型:MOSFET;驱动通道数:2;灌电流(IOL):-;拉电流(IOH):-;工作电压:2.7V~5.5V;上升时间(tr):-;下降时间(tf):12ns;; Manufacturer: SKYWORKS/SILICON LABS(芯科); AddInBom: yes; ModelId: 2da8125c657e49328ba6fa7b098653dd0819f05c4eef4c71ace90d822a990e87; ModelName: SOIC-16_L10.3-W7.5-H2.7-LS10.3-P1.27; ModelTransform: 405.511,409.68154,0,0,0,0,-0.0005,0,0; Driven Configuration: 低边；高边; Load Type: MOSFET; Number of Drivers: 2; Fall Time: 12ns; Quiescent Current(Iq): 2mA
U11 = HS96L03W2C03: 核心芯片:SSD1315芯片;接口类型:I2C;尺寸(inch):0.96;像素分辨率:128x64;; Manufacturer: HS(汉昇); 3D Model: bb65183306db4ca69fb52250be49b00e0819f05c4eef4c71ace90d822a990e87; 3D Model Transform: 1070.864,1094.486,0,0,0,0,0,-498.424,0; Interface: I2C; Dot Pixels: 128x64; Type of Drive: 无源(PMOLED); Display Range: 21.744x10.864mm; Display Color: 白色; Luminance: 180cd/m2; AddInBom: yes
U12 = AMS1117-5.0_C6187: 输出类型:固定;工作电压:15V;输出电压:5V;输出电流:1A;电源纹波抑制比(PSRR):60dB;输出极性:正极;; Manufacturer: AMS; AddInBom: yes; ModelId: 925194bf9823436183a3e0b978a8d0760819f05c4eef4c71ace90d822a990e87; ModelName: SOT-223-4P_L6.5-W3.5-H1.6-LS7.0-P2.30; ModelTransform: 279.89794,255.905,0,180,0,0,0.0005,0.0005,0; Output Type: 固定; Voltage - Supply: 15V; Output Voltage: 5V; Output Current: 1A; Power Supply Rejection Ratio (PSRR): 60dB; Voltage Dropout: 1.3V; Output Configuration: 正极; Number of Outputs: 1
U13 = AMS1117-3.3_C6186: 输出类型:固定;工作电压:15V;输出电压:3.3V;输出电流:1A;电源纹波抑制比(PSRR):72dB@(120Hz);输出极性:正极;; Manufacturer: AMS; AddInBom: yes; ModelId: 925194bf9823436183a3e0b978a8d0760819f05c4eef4c71ace90d822a990e87; ModelName: SOT-223-4P_L6.5-W3.5-H1.6-LS7.0-P2.30; ModelTransform: 279.89794,255.905,0,180,0,0,-3.9385,-0.0005,0; Output Type: 固定; Voltage - Supply: 15V; Output Voltage: 3.3V; Output Current: 1A; Voltage Dropout: 1.1V@(800mA); standby current: 5mA; Noise: 0.003%Vout; Output Configuration: 正极; Number of Outputs: 1
U14 U15 = MFP-25BRD52-33K: 电阻类型:金属膜电阻;阻值:33kΩ;精度:±0.1%;功率:250mW;温度系数:±25ppm/℃;; Manufacturer: YAGEO(国巨); AddInBom: yes; ModelId: 463263665006444ab7a47bd11b0cf9560819f05c4eef4c71ace90d822a990e87; ModelTransform: 427.165,94.32816,0,0,0,0,0,0,-196.85; Tolerance: ±0.1%; Power(Watts): 250mW
U16 = XL7005A: 功能类型:降压型;工作电压:5V~80V;输出电压:1.25V~20V;输出电流:400mA;输出类型:可调;; Manufacturer: XLSEMI(芯龙); AddInBom: yes; ModelId: 2424bcfd05224efdb78db06799097c7b0819f05c4eef4c71ace90d822a990e87; ModelTransform: 192.913,236.22,0,0,0,0,0,0,0; Function: 降压型; Voltage - Supply: 5V~80V; Output Current: 400mA; Frequency - Switching: 150kHz; Synchronous Rectifier: 否; Number of Outputs: 1; Topology: 降压式; Quiescent Current: 2.5mA; Switch tube (built-in/external): 内置; Output Type: 可调
U24 = LCKFB-DKX-STM32F103C8T6: 搭载Contex M3内核,程序存储容量64KB,RAM总容量20KB,最高72MHz主频,提供高效的计算能力和稳定的运行环境。; Manufacturer: 立创开发板; AddInBom: yes; ModelId: 70cdd142a616427fa7f75b03dcb285590819f05c4eef4c71ace90d822a990e87; ModelTransform: 2310.042,898.9982,0,0,0,0,90.551,0,-236.22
